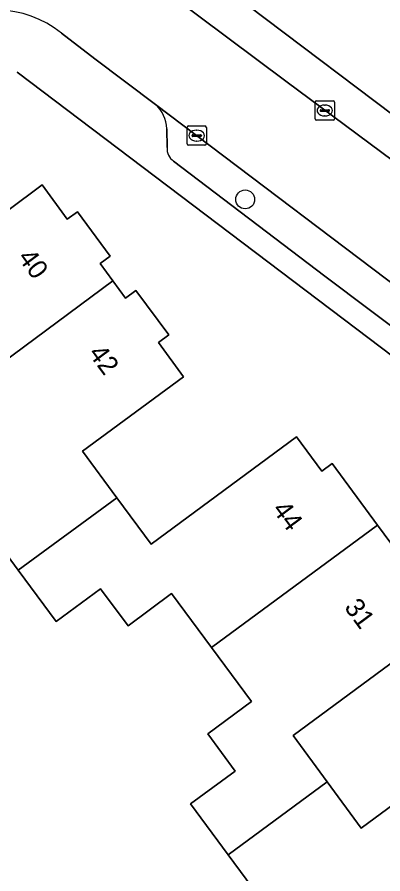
# Model space of a CAD drawing. Extents: x 163426 to 164192, y 380329 to 381641.
# Drawn here: x 163877.32 to 163896.26, y 381163.93 to 381208.26 of the extents above; entities that cross this region are included whole.
import ezdxf

# ---------------------------------------------------------------- set-up
doc = ezdxf.new("R2010")
doc.units = 0
for name, color, linetype in [('IMGEO_Boom', 7, 'Continuous'), ('IMGEO_Erf', 7, 'Continuous'), ('IMGEO_Kolk', 7, 'Continuous'), ('IMGEO_Pand', 7, 'Continuous'), ('IMGEO_Pand_nummerreeks', 7, 'Continuous'), ('IMGEO_Parkeervlak_open', 7, 'Continuous'), ('IMGEO_Rijbaan_lokaal_open', 7, 'Continuous'), ('IMGEO_Voetpad_open', 7, 'Continuous')]:
    doc.layers.add(name, color=color, linetype=linetype)

msp = doc.modelspace()

# ---------------------------------------------------------------- linework, layer by layer
at = {"layer": 'IMGEO_Boom'}
msp.add_circle((163889.127, 381198.828), 0.489, dxfattribs=at)
at = {"layer": 'IMGEO_Erf'}
for points in [[(163886.426, 381211.021), (163905.272, 381196.785)], [(163897.466, 381190.189), (163877.319, 381205.411)], [(163875.035, 381196.931), (163878.618, 381199.573), (163879.914, 381197.798), (163880.446, 381198.187), (163882.142, 381195.898), (163881.612, 381195.505), (163882.273, 381194.614), (163882.934, 381193.722), (163883.464, 381194.115), (163885.166, 381191.818), (163884.634, 381191.429), (163885.932, 381189.655), (163880.703, 381185.796), (163882.478, 381183.391), (163884.252, 381180.986), (163891.786, 381186.545), (163893.099, 381184.769), (163893.632, 381185.163), (163895.984, 381181.97), (163898.336, 381178.777)], [(163891.621, 381160.344), (163888.24, 381164.922), (163886.3, 381167.548), (163888.607, 381169.253), (163887.188, 381171.174), (163889.447, 381172.843), (163887.383, 381175.637), (163885.319, 381178.431), (163883.06, 381176.762), (163881.641, 381178.683), (163879.341, 381176.985), (163877.381, 381179.639), (163874.02, 381184.189)], [(163899.116, 381176.624), (163891.604, 381171.094), (163893.368, 381168.698), (163895.131, 381166.302), (163900.332, 381170.131)]]:
    msp.add_lwpolyline(points, dxfattribs=at)
at = {"layer": 'IMGEO_Kolk'}
for p, q in [((163892.747, 381203), (163892.747, 381203.852)), ((163892.822, 381203.926), (163893.674, 381203.926)), ((163893.748, 381203.852), (163893.748, 381203)), ((163893.006, 381203.42), (163893.006, 381203.432)), ((163893.444, 381203.383), (163893.046, 381203.383)), ((163893.049, 381203.469), (163893.447, 381203.469)), ((163893.235, 381203.706), (163893.26, 381203.706)), ((163893.49, 381203.432), (163893.49, 381203.42)), ((163893.674, 381202.926), (163892.822, 381202.926)), ((163893.258, 381203.146), (163893.233, 381203.146)), ((163886.115, 381201.7), (163886.115, 381202.552)), ((163886.19, 381202.626), (163887.042, 381202.626)), ((163887.116, 381202.552), (163887.116, 381201.7)), ((163886.374, 381202.12), (163886.374, 381202.132)), ((163886.812, 381202.083), (163886.414, 381202.083)), ((163886.417, 381202.169), (163886.815, 381202.169)), ((163886.603, 381202.406), (163886.628, 381202.406)), ((163886.858, 381202.132), (163886.858, 381202.12)), ((163887.042, 381201.626), (163886.19, 381201.626)), ((163886.626, 381201.846), (163886.601, 381201.846))]:
    msp.add_line(p, q, dxfattribs=at)
for points in [[(163892.747, 381203), (163892.747, 381203.852)], [(163892.822, 381203.926), (163893.674, 381203.926)], [(163893.748, 381203.852), (163893.748, 381203)], [(163893.674, 381202.926), (163892.822, 381202.926)], [(163886.115, 381201.7), (163886.115, 381202.552)], [(163886.19, 381202.626), (163887.042, 381202.626)], [(163887.116, 381202.552), (163887.116, 381201.7)], [(163887.042, 381201.626), (163886.19, 381201.626)]]:
    msp.add_lwpolyline(points, dxfattribs=at)
for centre, radius, start, end in [((163892.824, 381203.85), 0.0765, 91.552, 178.448), ((163892.824, 381203.85), 0.0765, 91.552, 178.448), ((163893.672, 381203.85), 0.0765, 1.552, 88.448), ((163893.672, 381203.85), 0.0765, 1.552, 88.448), ((163893.046, 381203.429), 0.0403, 85.8775, 175.7526), ((163893.043, 381203.419), 0.0366, 178.938, 274.7102), ((163893.447, 381203.426), 0.043, 264.8664, 352.4533), ((163893.451, 381203.431), 0.0386, 1.7309, 96.639), ((163892.824, 381203.002), 0.0765, 181.552, 268.448), ((163892.824, 381203.002), 0.0765, 181.552, 268.448), ((163893.672, 381203.002), 0.0765, 271.552, 358.448), ((163893.672, 381203.002), 0.0765, 271.552, 358.448), ((163886.192, 381202.55), 0.0765, 91.552, 178.448), ((163886.192, 381202.55), 0.0765, 91.552, 178.448), ((163887.04, 381202.55), 0.0765, 1.552, 88.448), ((163887.04, 381202.55), 0.0765, 1.552, 88.448), ((163886.414, 381202.129), 0.0403, 85.8775, 175.7526), ((163886.411, 381202.119), 0.0366, 178.938, 274.7102), ((163886.815, 381202.126), 0.043, 264.8664, 352.4533), ((163886.819, 381202.131), 0.0386, 1.7309, 96.639), ((163886.192, 381201.702), 0.0765, 181.552, 268.448), ((163886.192, 381201.702), 0.0765, 181.552, 268.448), ((163887.04, 381201.702), 0.0765, 271.552, 358.448), ((163887.04, 381201.702), 0.0765, 271.552, 358.448)]:
    msp.add_arc(centre, radius, start, end, dxfattribs=at)
for centre, major_axis, ratio, start_param, end_param in [((163893.234, 381203.426), (-0.387, 0.002), 0.722429, 4.712389, 7.853982), ((163893.259, 381203.426), (-0.39, 0.002), 0.717154, 1.570796, 4.712389), ((163886.602, 381202.126), (-0.387, 0.002), 0.722429, 4.712389, 7.853982), ((163886.627, 381202.126), (-0.39, 0.002), 0.717154, 1.570796, 4.712389)]:
    msp.add_ellipse(centre, major_axis=major_axis, ratio=ratio, start_param=start_param, end_param=end_param, dxfattribs=at)
at = {"layer": 'IMGEO_Pand'}
for points in [[(163882.273, 381194.614), (163881.612, 381195.505), (163882.142, 381195.898), (163880.446, 381198.187), (163879.914, 381197.798), (163878.618, 381199.573), (163875.035, 381196.931), (163873.343, 381195.683), (163871.43, 381198.277), (163866.377, 381194.536), (163869.347, 381190.515), (163869.893, 381189.776), (163872.144, 381191.439), (163874.207, 381188.646)], [(163877.381, 381179.639), (163882.478, 381183.391), (163880.703, 381185.796), (163885.932, 381189.655), (163884.634, 381191.429), (163885.166, 381191.818), (163883.464, 381194.115), (163882.934, 381193.722), (163882.273, 381194.614), (163874.207, 381188.646), (163876.271, 381185.852), (163874.02, 381184.189)], [(163887.383, 381175.637), (163895.984, 381181.97), (163893.632, 381185.163), (163893.099, 381184.769), (163891.786, 381186.545), (163884.252, 381180.986), (163882.478, 381183.391), (163877.381, 381179.639), (163879.341, 381176.985), (163881.641, 381178.683), (163883.06, 381176.762), (163885.319, 381178.431)], [(163887.383, 381175.637), (163889.447, 381172.843), (163887.188, 381171.174), (163888.607, 381169.253), (163886.3, 381167.548), (163888.24, 381164.922), (163893.368, 381168.698), (163891.604, 381171.094), (163899.116, 381176.624), (163897.808, 381178.385), (163898.336, 381178.777), (163895.984, 381181.97)], [(163893.368, 381168.698), (163888.24, 381164.922), (163891.621, 381160.344), (163893.872, 381162.007), (163895.936, 381159.214), (163904.008, 381165.174), (163903.352, 381166.064), (163903.884, 381166.456), (163902.178, 381168.769), (163901.651, 381168.373), (163900.332, 381170.131), (163895.131, 381166.302)]]:
    msp.add_lwpolyline(points, close=True, dxfattribs=at)
at = {"layer": 'IMGEO_Parkeervlak_open'}
for points in [[(163901.246, 381191.072), (163899.28, 381192.557), (163884.483, 381203.733)], [(163885.07, 381202.483), (163885.086, 381201.514)], [(163885.421, 381200.802), (163893.254, 381194.864), (163898.057, 381191.243)]]:
    msp.add_lwpolyline(points, dxfattribs=at)
for centre, radius, start, end in [((163883.334, 381202.431), 1.737, 1.73, 48.5795), ((163885.863, 381201.445), 0.78, 174.9107, 235.4837)]:
    msp.add_arc(centre, radius, start, end, dxfattribs=at)
at = {"layer": 'IMGEO_Rijbaan_lokaal_open'}
msp.add_lwpolyline([(163879.612, 381207.432), (163881.341, 381206.105), (163884.483, 381203.733), (163899.28, 381192.557), (163902.32, 381196.718), (163891.228, 381204.941), (163885.22, 381209.452), (163882.652, 381211.418), (163882.481, 381211.582)], dxfattribs=at)
msp.add_arc((163876.225, 381203.225), 5.401, 51.1627, 126.7068, dxfattribs=at)
at = {"layer": 'IMGEO_Voetpad_open'}
for points in [[(163905.272, 381196.785), (163886.426, 381211.021), (163885.917, 381211.405), (163882.603, 381213.933), (163876.336, 381218.714), (163835.008, 381188.174)], [(163883.113, 381212.461), (163882.481, 381211.582), (163882.652, 381211.418), (163885.22, 381209.452), (163891.228, 381204.941), (163902.32, 381196.718), (163902.511, 381196.972)], [(163884.483, 381203.733), (163881.341, 381206.105), (163879.612, 381207.432)], [(163877.319, 381205.411), (163897.466, 381190.189), (163898.057, 381191.243), (163893.254, 381194.864), (163885.421, 381200.802)], [(163885.086, 381201.514), (163885.07, 381202.483)]]:
    msp.add_lwpolyline(points, dxfattribs=at)
for centre, radius, start, end in [((163876.225, 381203.225), 5.401, 51.1627, 126.7068), ((163883.334, 381202.431), 1.737, 1.73, 48.5795), ((163885.863, 381201.445), 0.78, 174.9107, 235.4837)]:
    msp.add_arc(centre, radius, start, end, dxfattribs=at)

# ---------------------------------------------------------------- texts
at = {"layer": 'IMGEO_Pand_nummerreeks'}
for s, rotation, p in [('40', 306.4055, (163877.318, 381195.809)), ('42', 306.4068, (163880.972, 381190.855)), ('44', 306.4756, (163890.492, 381182.778)), ('31', 306.6035, (163894.22, 381177.714))]:
    msp.add_text(s, height=1, rotation=rotation, dxfattribs=at).set_placement(p)

doc.saveas('drawing.dxf')
